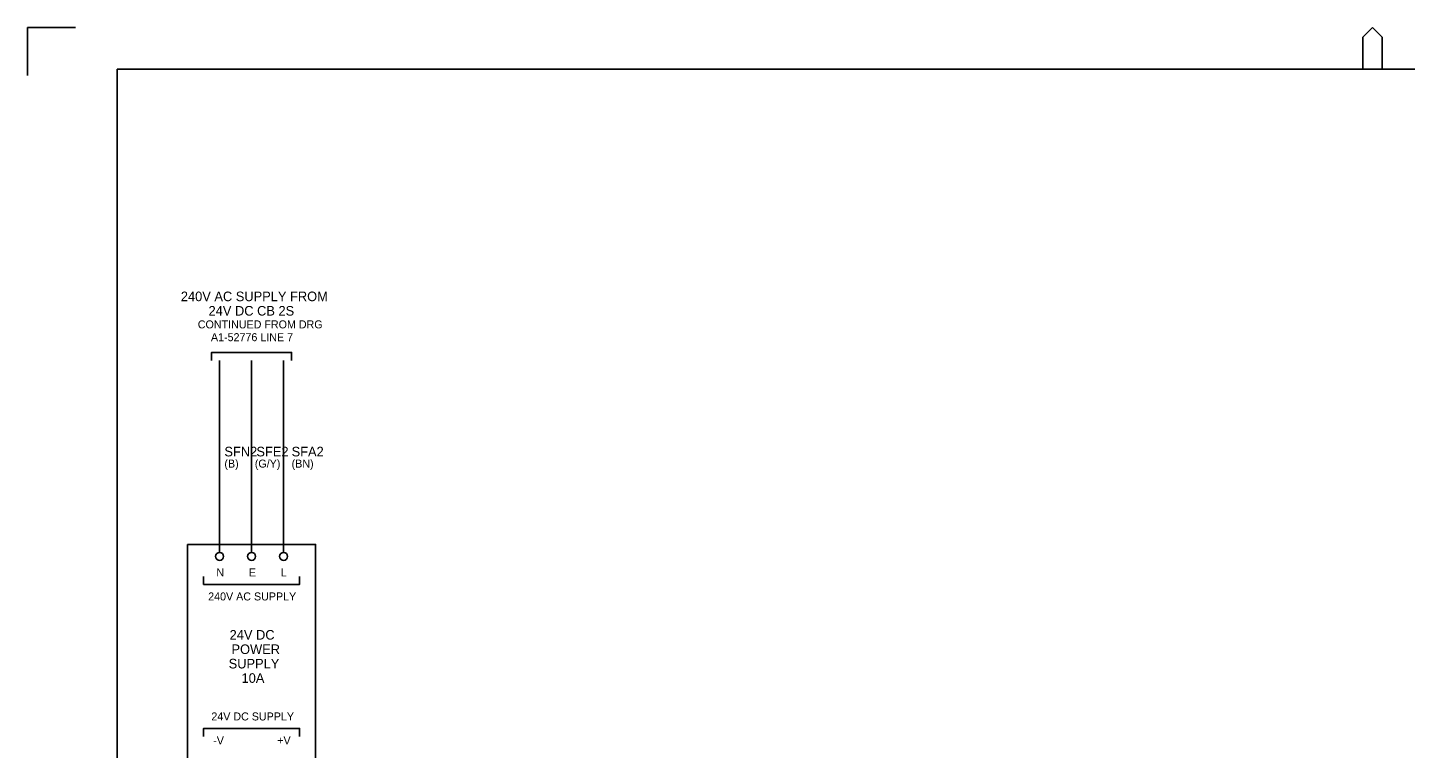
# Model space of a CAD drawing. Extents: x 0 to 841, y 0 to 594.
# Drawn here: x 0 to 430.5, y 368.8 to 594 of the extents above; entities that cross this region are included whole.
import ezdxf

# ---------------------------------------------------------------- set-up
doc = ezdxf.new("R2010")
doc.units = 0
for name, color, linetype in [('A1BORDER', 7, 'Continuous'), ('Level 1', 7, 'Continuous'), ('Level 4', 7, 'Continuous')]:
    doc.layers.add(name, color=color, linetype=linetype)

msp = doc.modelspace()

# ---------------------------------------------------------------- linework, layer by layer
at = {"layer": 'A1BORDER'}
for p, q in [((0, 594), (15, 594)), ((0, 579), (0, 594)), ((417.19, 591), (420.19, 594)), ((417.19, 581), (417.19, 591)), ((423.19, 591), (420.19, 594)), ((423.19, 581), (423.19, 591)), ((28, 581), (829, 581)), ((28, 581), (28, 15))]:
    msp.add_line(p, q, dxfattribs=at)
at = {"layer": 'Level 1'}
for p, q in [((60, 490), (60, 430)), ((70, 490), (70, 430)), ((80, 490), (80, 430))]:
    msp.add_line(p, q, dxfattribs=at)
for points in [[(57.5, 490), (57.5, 492.5), (82.5, 492.5), (82.5, 490)], [(55, 422.5), (55, 420), (85, 420), (85, 422.5)], [(55, 372.5), (55, 375), (85, 375), (85, 372.5)]]:
    msp.add_lwpolyline(points, dxfattribs=at)
msp.add_lwpolyline([(50, 432.5), (90, 432.5), (90, 362.5), (50, 362.5)], close=True, dxfattribs=at)
at = {"layer": 'Level 4'}
for centre in [(60, 428.75), (70, 428.75), (80, 428.75)]:
    msp.add_circle(centre, 1.25, dxfattribs=at)

# ---------------------------------------------------------------- texts
at = {"layer": 'Level 1'}
for s, height, p in [('240V AC SUPPLY FROM', 3, (47.89, 508.5)), ('24V DC CB 2S', 3, (56.55, 504)), ('CONTINUED FROM DRG', 2.5, (53.19, 500)), ('A1-52776 LINE 7', 2.5, (57.3, 496)), ('SFN2', 3, (61.5, 460)), ('SFE2', 3, (71.5, 460)), ('SFA2', 3, (82.5, 460)), ('(B)', 2.5, (61.5, 456.5)), ('(G/Y)', 2.5, (71, 456.5)), ('(BN)', 2.5, (82.5, 456.5)), ('N', 2.5, (59, 422.5)), ('E', 2.5, (69.13, 422.5)), ('L', 2.5, (79.13, 422.5)), ('240V AC SUPPLY', 2.5, (56.43, 415)), ('24V DC', 3, (63.13, 402.75)), ('POWER', 3, (63.72, 398.25)), ('SUPPLY', 3, (62.83, 393.75)), ('10A', 3, (66.86, 389.25)), ('24V DC SUPPLY', 2.5, (57.42, 377.5)), ('-V', 2.5, (58.01, 370)), ('+V', 2.5, (78.01, 370))]:
    msp.add_text(s, height=height, dxfattribs=at).set_placement(p)

doc.saveas('drawing.dxf')
